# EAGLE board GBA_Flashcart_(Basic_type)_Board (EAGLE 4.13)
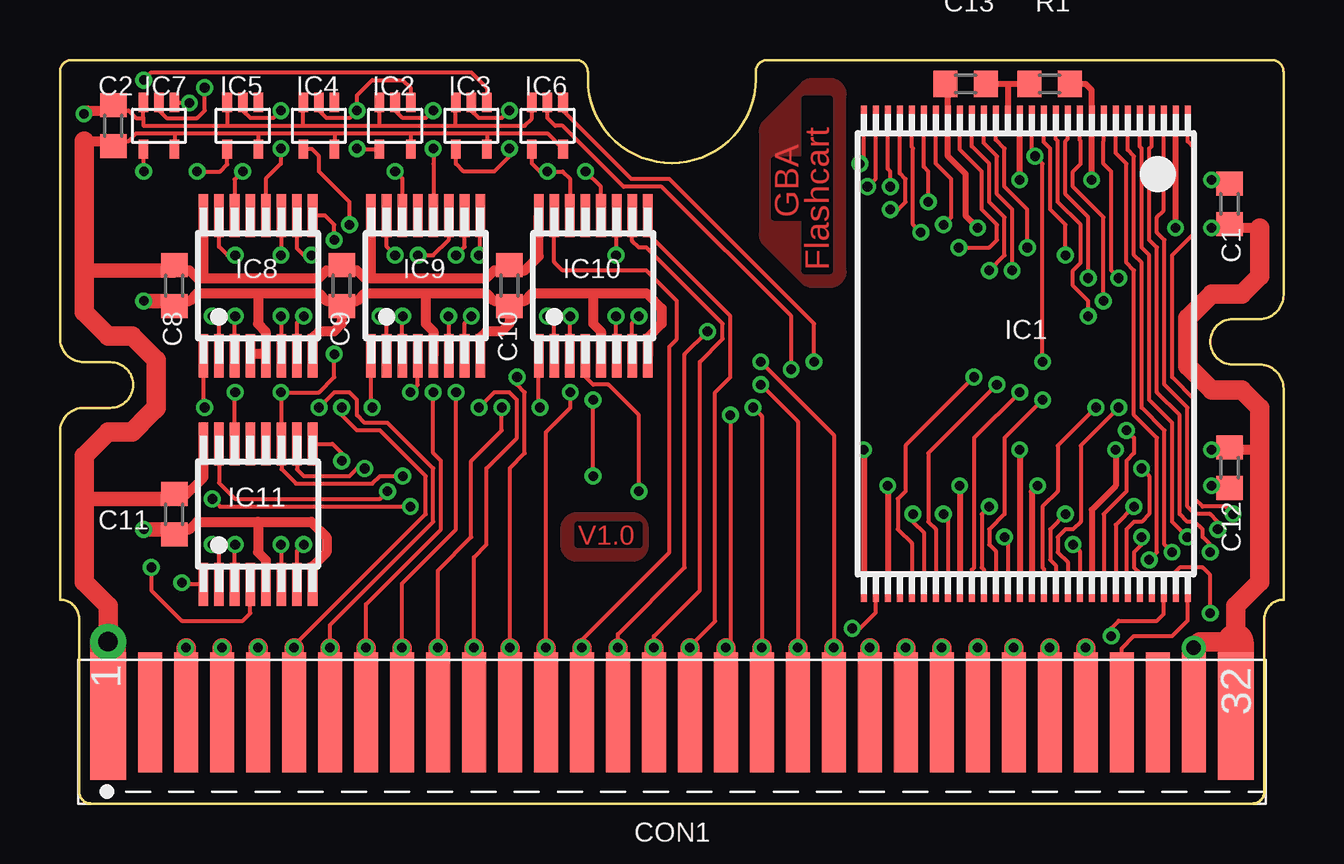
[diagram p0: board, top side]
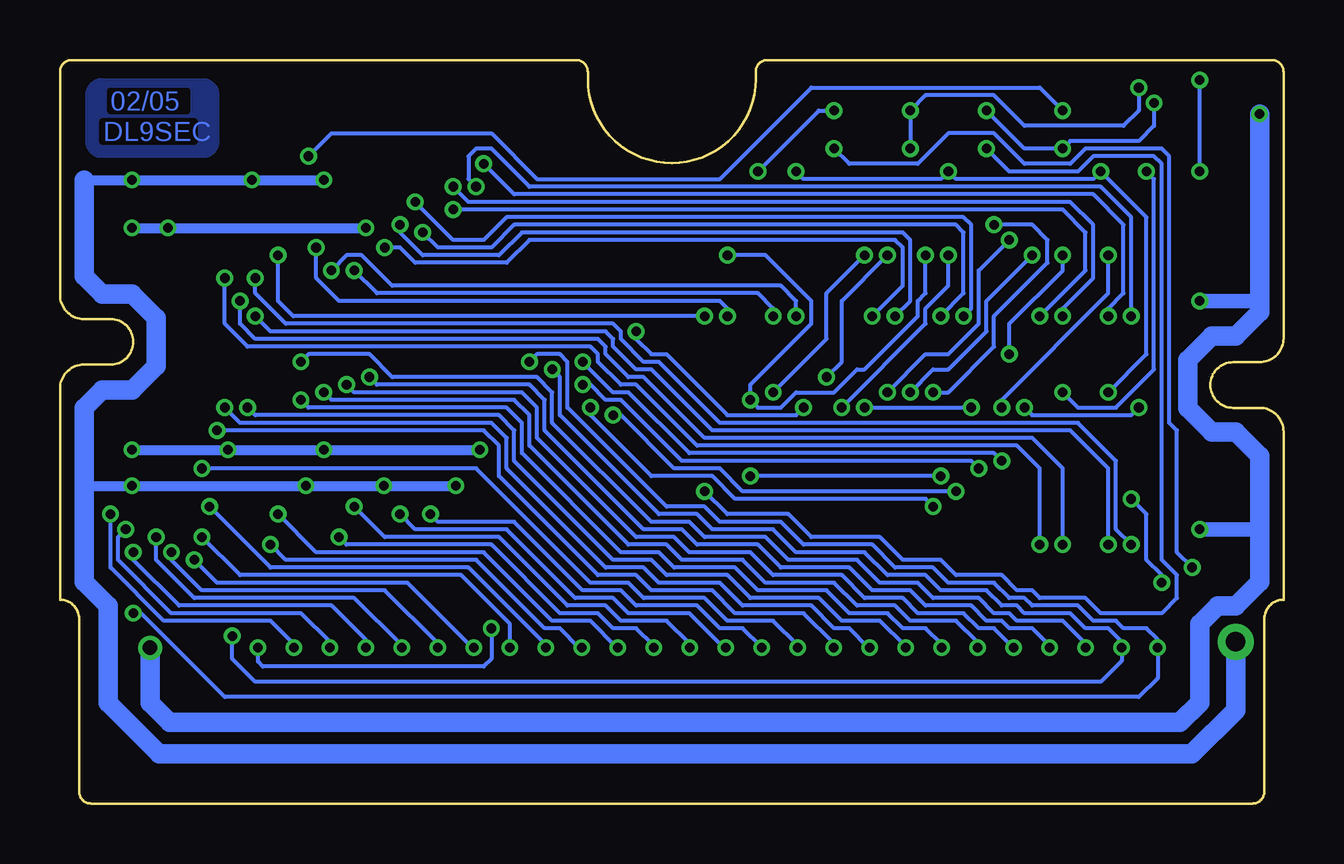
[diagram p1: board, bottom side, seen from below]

Size 51 x 31 mm. Coordinates in mm from the lower left corner, seen from the top.
Outline: 0.8,7.7 arc90 0,8.5 0,15.5 arc-90 1,16.5 2.1,16.5 arc180 2.1,18.4 1,18.4 arc-90 0,19.4 0,30.5 arc-90 0.5,31 21.5,31 arc-90 22,30.5 22,30.2 arc90 25.5,26.7 arc90 29,30.2 29,30.5 arc-90 29.5,31 50.5,31 arc-90 51,30.5 51,21.2 arc-90 50,20.2 48.9,20.2 arc180 48.9,18.3 50,18.3 arc-90 51,17.3 51,8.5 arc90 50.2,7.7 50.2,0.5 arc-90 49.7,0 1.3,0 arc-90 0.8,0.5 0.8,7.7
Copper layers (1*16): Top 0.035mm / dielectric 1.5mm / Bottom 0.035mm
Design rules "PCB-POOL": minimum track width 6mil, minimum drill 12mil, track to track 6mil, track to pad 6mil, pad to pad 6mil, via to via 6mil, smd to smd 6mil, copper to edge 18mil, drill to drill 8mil, minimum pad ring 8mil, minimum via ring 6mil, stop-mask expansion 3mil, vias tented up to drill 0mil, thermal gap 8mil

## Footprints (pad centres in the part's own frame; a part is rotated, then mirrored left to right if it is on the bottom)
0603 = smd 1 x 1.1: 1 -0.85,0; 2 0.85,0
GBACARTCON = smd 1.5 x 5.3: 1 1.25,3.65; 32 48.25,3.65 | smd 1 x 5: 2 3,3.8; 3 4.5,3.8; 4 6,3.8; 5 7.5,3.8; 6 9,3.8; 7 10.5,3.8; 8 12,3.8; 9 13.5,3.8; 10 15,3.8; 11 16.5,3.8; 12 18,3.8; 13 19.5,3.8; 14 21,3.8; 15 22.5,3.8; 16 24,3.8; 17 25.5,3.8; 18 27,3.8; 19 28.5,3.8; 20 30,3.8; 21 31.5,3.8; 22 33,3.8; 23 34.5,3.8; 24 36,3.8; 25 37.5,3.8; 26 39,3.8; 27 40.5,3.8; 28 42,3.8; 29 43.5,3.8; 30 45,3.8; 31 46.5,3.8
TSOP56 = smd 1.2 x 0.25: 1 -9.75,6.75; 2 -9.75,6.25; 3 -9.75,5.75; 4 -9.75,5.25; 5 -9.75,4.75; 6 -9.75,4.25; 7 -9.75,3.75; 8 -9.75,3.25; 9 -9.75,2.75; 10 -9.75,2.25; 11 -9.75,1.75; 12 -9.75,1.25; 13 -9.75,0.75; 14 -9.75,0.25; 15 -9.75,-0.25; 16 -9.75,-0.75; 17 -9.75,-1.25; 18 -9.75,-1.75; 19 -9.75,-2.25; 20 -9.75,-2.75; 21 -9.75,-3.25; 22 -9.75,-3.75; 23 -9.75,-4.25; 24 -9.75,-4.75; 25 -9.75,-5.25; 26 -9.75,-5.75; 27 -9.75,-6.25; 28 -9.75,-6.75; 29 9.75,-6.75; 30 9.75,-6.25; 31 9.75,-5.75; 32 9.75,-5.25; 33 9.75,-4.75; 34 9.75,-4.25; 35 9.75,-3.75; 36 9.75,-3.25; 37 9.75,-2.75; 38 9.75,-2.25; 39 9.75,-1.75; 40 9.75,-1.25; 41 9.75,-0.75; 42 9.75,-0.25; 43 9.75,0.25; 44 9.75,0.75; 45 9.75,1.25; 46 9.75,1.75; 47 9.75,2.25; 48 9.75,2.75; 49 9.75,3.25; 50 9.75,3.75; 51 9.75,4.25; 52 9.75,4.75; 53 9.75,5.25; 54 9.75,5.75; 55 9.75,6.25; 56 9.75,6.75
SOT353 = smd 0.4 x 0.8: 1 -0.65,-0.975; 2 0,-0.975; 3 0.65,-0.975; 4 0.65,0.975; 5 -0.65,0.975
TSSOP16 = smd 1.8 x 0.4: 1 -2.925,2.275; 2 -2.925,1.625; 3 -2.925,0.975; 4 -2.925,0.325; 5 -2.925,-0.325; 6 -2.925,-0.975; 7 -2.925,-1.625; 8 -2.925,-2.275; 9 2.925,-2.275; 10 2.925,-1.625; 11 2.925,-0.975; 12 2.925,-0.325; 13 2.925,0.325; 14 2.925,0.975; 15 2.925,1.625; 16 2.925,2.275

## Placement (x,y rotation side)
C1  100nF  [0603]  48.75,25 270 top
C2  100nF  [0603]  2.22,28.26 90 top
C8  100nF  [0603]  4.76,21.59 270 top
C9  100nF  [0603]  11.75,21.59 270 top
C10  100nF  [0603]  18.73,21.59 270 top
C11  100nF  [0603]  4.76,12.06 270 top
C12  100nF  [0603]  48.75,14 90 top
C13  opt.  [0603]  37.75,30 180 top
CON1  GBACARTCON  [GBACARTCON]  0.75,0 0 top
IC1  TE28F128J3C-120  [TSOP56]  40.25,18.75 270 top
IC2  74LVC1G00GW  [SOT353]  13.97,28.26 180 top
IC3  74LVC1G00GW  [SOT353]  17.14,28.26 180 top
IC4  74LVC1G04GW  [SOT353]  10.79,28.26 180 top
IC5  74LVC1G04GW  [SOT353]  7.62,28.26 180 top
IC6  74LVC1G08GW  [SOT353]  20.32,28.26 180 top
IC7  74LVC1G08GW  [SOT353]  4.13,28.26 180 top
IC8  74AC191MTC  [TSSOP16]  8.26,21.59 90 top
IC9  74AC191MTC  [TSSOP16]  15.24,21.59 90 top
IC10  74AC191MTC  [TSSOP16]  22.23,21.59 90 top
IC11  74AC191MTC  [TSSOP16]  8.26,12.06 90 top
R1  1k  [0603]  41.25,30 0 top

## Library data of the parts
C1 C2 C8-C13 R1 = Custom_II
CON1 = GBA_Cart
IC1-IC11 = GBA_Parts

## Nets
+3V3: C1.1 C2.1 C8.1 C9.1 C10.1 C11.1 C12.1 CON1.1 IC1.9 IC1.15 IC1.31 IC1.37 IC1.43 IC2.5 IC3.5 IC4.5 IC5.5 IC6.5 IC7.5 IC8.16 IC9.16 IC10.16 IC11.16 R1.2
A16: CON1.22 IC1.7
A17: CON1.23 IC1.6
A18: CON1.24 IC1.5
A19: CON1.25 IC1.4
A20: CON1.26 IC1.3
A21: CON1.27 IC1.1
A22: CON1.28 IC1.30
A23: CON1.29 IC1.56
AD0: CON1.6 IC1.33 IC8.15
AD1: CON1.7 IC1.35 IC8.1
AD2: CON1.8 IC1.38 IC8.10
AD3: CON1.9 IC1.40 IC8.9
AD4: CON1.10 IC1.44 IC9.15
AD5: CON1.11 IC1.46 IC9.1
AD6: CON1.12 IC1.49 IC9.10
AD7: CON1.13 IC1.51 IC9.9
AD8: CON1.14 IC1.34 IC10.15
AD9: CON1.15 IC1.36 IC10.1
AD10: CON1.16 IC1.39 IC10.10
AD11: CON1.17 IC1.41 IC10.9
AD12: CON1.18 IC1.45 IC11.15
AD13: CON1.19 IC1.47 IC11.1
AD14: CON1.20 IC1.50 IC11.10
AD15: CON1.21 IC1.52 IC11.9
ADR0: IC1.28 IC8.3
ADR1: IC1.27 IC8.2
ADR2: IC1.26 IC8.6
ADR3: IC1.25 IC8.7
ADR4: IC1.24 IC9.3
ADR5: IC1.23 IC9.2
ADR6: IC1.22 IC9.6
ADR7: IC1.20 IC9.7
ADR8: IC1.19 IC10.3
ADR9: IC1.18 IC10.2
ADR10: IC1.17 IC10.6
ADR11: IC1.13 IC10.7
ADR12: IC1.12 IC11.3
ADR13: IC1.11 IC11.2
ADR14: IC1.10 IC11.6
ADR15: IC1.8 IC11.7
GND: C1.2 C2.2 C8.2 C9.2 C10.2 C11.2 C12.2 C13.2 CON1.31 CON1.32 IC1.2 IC1.21 IC1.29 IC1.42 IC1.48 IC2.3 IC3.3 IC4.3 IC5.3 IC6.3 IC7.3 IC8.4 IC8.5 IC8.8 IC9.5 IC9.8 IC10.5 IC10.8 IC11.5 IC11.8
N$1: IC5.4 IC8.11 IC9.11 IC10.11 IC11.11
N$2: IC6.4 IC8.14 IC9.14 IC10.14 IC11.14
N$3: IC3.4 IC11.4
N$4: C13.1 IC1.16 R1.1
N$5: IC4.4 IC9.4
N$6: IC2.1 IC4.2 IC7.1 IC8.12
N$7: IC2.4 IC10.4
N$8: IC2.2 IC7.2 IC9.12
N$9: IC3.2 IC10.12
N$10: IC3.1 IC7.4
NCS_ROM: CON1.5 IC1.14 IC5.2
NRD: CON1.4 IC1.54 IC6.2
NWR: CON1.3 IC1.55 IC6.1

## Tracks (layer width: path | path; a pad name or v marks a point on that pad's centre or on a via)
+3V3  (via drill 0.4, 0.8 pad 1.5)
  Top 0.16: 1,27.62 0.95,27.62 | IC5.5 8.27,27.93 8.26,27.94 | C2.1 2.22,27.62 2.86,27.62 3.17,27.94 4.76,27.94 | IC6.5 20.32,27.94 17.78,27.94 | 4.76,27.94 8.26,27.94 | 8.26,27.94 11.43,27.94 | 11.43,27.94 14.61,27.94 | 14.61,27.94 17.78,27.94 | IC3.5 17.8,27.93 17.78,27.94 | IC2.5 14.62,27.93 14.61,27.94 | IC4.5 11.45,27.93 11.43,27.94 | IC7.5 4.78,27.93 4.76,27.94
  Top 0.25: v34.5,13.25 IC1.31 | v40.75,13.25 40.5,13 IC1.43 | 48.75,13.25 C12.1 | v43,26 IC1.9 43,29.75 42.75,30 R1.2 | v40,26 IC1.15 | C1.1 48.75,25.5 | v37.5,13.25 IC1.37 v37.5,13.25
  Top 0.406: v48,13.25 48.75,13.25 48.75,13 | v48,26 48.75,26 | 1,23.5 0.95,23.5 | 1,13.34 0.95,13.34 | 1,22.23 0.95,22.23 | 18.52,22.23 C10.1 18.73,22.23 | 1,12.7 0.95,12.7 | C11.1 4.76,12.7 5.08,12.7 5.98,13.6 IC11.16 | 1,27.62 2.22,27.62 | C8.1 4.76,22.23 5.4,22.23 5.71,21.91 6.03,21.91 | 6.03,21.91 10.79,21.91 11.11,22.23 11.75,22.23 | 11.75,22.23 C9.1 | IC8.16 5.98,21.96 6.03,21.91 | 11.75,22.23 12.38,22.23 12.7,21.91 13.02,21.91 | 13.02,21.91 17.78,21.91 18.1,22.23 18.73,22.23 | IC9.16 12.96,21.96 13.02,21.91 | 18.73,22.23 19.37,22.23 19.95,22.81 IC10.16 | 3.75,16.25
  Top 0.6: 1,12.7 4.76,12.7 | 1,22.23 4.76,22.23
  Top 0.61: C12.1 48.75,13 | 48.75,26 C1.1
  Top 0.813: v2,6.75 2,8.25 1,9.25 1,12.7 1,13.34 1,14.5 2,15.5 3,15.5 3.75,16.25 4,16.5 4,18.5 3,19.5 2,19.5 1,20.5 1,22.23 1,23.5 1,27.62
  Top 1.5: CON1.1 v2,6.75
  Bottom 0.406: v34.5,13.25 v37.5,13.25 v40.75,13.25 v48,13.25 50,13.25 | v40,26 v43,26 v48,26 50,26
  Bottom 0.813: v2,6.75 2,3.88 3.82,2.07 46.87,2.07 49,4.2 49,8.25 50,9.25 50,13.25 50,16.5 49.25,17.25 48,17.25 47,18.25 47,20.25 48,21.25 49.25,21.25 50,22 50,26
A16  (via drill 0.4)
  Top 0.16: IC1.7 44,27.12 44.45,26.67 44.45,22.54 44.77,22.23 44.77,16.19 45.72,15.24 45.72,10.48 v45.4,10.16
  Top 0.813: CON1.22 v33.75,6.5
  Bottom 0.16: v45.4,10.16 44.45,9.21 36.51,9.21 33.8,6.5 v33.75,6.5
A17  (via drill 0.4)
  Top 0.16: IC1.6 44.5,27.25 44.77,26.99 44.77,22.86 45.09,22.54 45.09,16.51 46.04,15.56 46.04,10.79 v46.35,10.48
  Top 0.813: CON1.23 v35.25,6.5
  Bottom 0.16: v46.35,10.48 46.35,10.16 45.09,8.89 37.47,8.89 35.25,6.67 v35.25,6.5
A18  (via drill 0.4)
  Top 0.16: v46.99,11.11 46.35,11.75 46.35,15.88 45.4,16.83 45.4,22.86 45.09,23.18 45.09,27.3 45,27.39 IC1.5
  Top 0.813: CON1.24 v36.75,6.5
  Bottom 0.16: v36.75,6.5 36.75,6.59 38.73,8.57 45.4,8.57 46.99,10.16 v46.99,11.11
A19  (via drill 0.4)
  Top 0.16: v47.94,10.48 47.94,10.79 47.62,11.11 47.62,11.43 47.31,11.75 46.99,11.75 46.67,12.06 46.67,16.19 45.72,17.14 45.72,23.18 45.4,23.5 45.4,27.3 45.5,27.4 IC1.4
  Top 0.813: CON1.25 v38.25,6.5
  Bottom 0.16: v38.25,6.5 38.25,6.82 39.69,8.26 46.04,8.26 47.94,10.16 v47.94,10.48
A20  (via drill 0.4)
  Top 0.16: v48.26,11.43 48.26,11.75 47.94,12.06 47.31,12.06 46.99,12.38 46.99,16.51 46.04,17.46 46.04,23.5 45.72,23.81 45.72,24.45 46,24.73 IC1.3
  Top 0.813: CON1.26 v39.75,6.5
  Bottom 0.16: v39.75,6.5 39.75,6.73 40.96,7.94 46.35,7.94 48.58,10.16 48.58,11.11 v48.26,11.43
A21  (via drill 0.4)
  Top 0.16: IC1.1 47,27.61 47.31,27.3 47.31,23.81 46.35,22.86 46.35,17.78 47.31,16.83 47.31,12.7 47.62,12.38 48.58,12.38 v48.9,12.06
  Top 0.813: CON1.27 v41.25,6.5
  Bottom 0.16: v41.25,6.5 41.25,6.64 42.23,7.62 46.67,7.62 48.9,9.84 v48.9,12.06
A22  (via drill 0.4)
  Top 0.16: IC1.30 34,7.96 33.34,7.3 v33.02,7.3
  Top 0.813: v42.75,6.5 CON1.28
  Bottom 0.16: v42.75,6.5 42.75,5.92 42.55,5.71 33.34,5.71 33.02,6.03 v33.02,7.3
A23
  Top 0.16: CON1.29 44.25,6.47 44.77,6.99 46.35,6.99 47,7.63 IC1.56
AD0  (via drill 0.4)
  Top 0.16: IC1.33 35.5,10.86 34.92,11.43 34.92,12.7 35.24,13.02 35.24,14.92 v38.1,17.78 | 9.75,6.58 v9.75,6.5 9.84,6.59 9.84,6.67 15.24,12.06 15.24,13.65 13.34,15.56 12.38,15.56 11.75,16.19 v11.75,16.51 | v7.3,22.86 6.99,22.86 6.63,23.21 IC8.15
  Top 0.813: CON1.6 v9.75,6.5
  Bottom 0.16: v38.1,17.78 37.78,17.46 31.43,17.46 30.8,16.83 30.8,15.56 26.67,11.43 25.08,11.43 24.45,10.79 21.91,10.79 20.95,9.84 18.1,9.84 17.14,8.89 15.56,8.89 14.92,8.26 13.02,8.26 12.38,7.62 11.75,7.62 11.43,7.3 10.48,7.3 9.75,6.58 v9.75,6.5 | v7.3,22.86 7.3,21.27 11.75,16.83 v11.75,16.51
AD1  (via drill 0.4)
  Top 0.16: IC1.35 36.5,11.44 36.2,11.75 36.2,14.61 v39.05,17.46 | IC8.1 5.98,16.56 v6.03,16.51 | v10.79,16.51 11.43,17.14 12.06,17.14 12.38,16.83 12.38,16.19 12.7,15.88 13.65,15.88 15.56,13.97 15.56,11.75 11.25,7.44 v11.25,6.5
  Top 0.813: CON1.7 v11.25,6.5
  Bottom 0.16: v39.05,17.46 38.73,17.14 31.75,17.14 31.11,16.51 31.11,15.24 26.99,11.11 25.4,11.11 24.77,10.48 22.23,10.48 21.27,9.53 18.41,9.53 17.46,8.57 15.88,8.57 15.24,7.94 13.34,7.94 12.7,7.3 12.06,7.3 11.26,6.5 v11.25,6.5 | v10.79,16.51 10.48,16.19 6.35,16.19 v6.03,16.51
AD2  (via drill 0.4)
  Top 0.16: IC1.38 38,9.74 38.1,9.84 38.1,15.24 v40.01,17.14 | v15.56,17.14 15.56,14.61 15.88,14.29 15.88,11.43 12.75,8.3 v12.75,6.5 | v10.48,22.86 10.16,22.86 9.88,23.14 IC8.10
  Top 0.813: CON1.8 v12.75,6.5
  Bottom 0.16: v40.01,17.14 39.69,16.83 32.07,16.83 31.43,16.19 31.43,14.92 27.3,10.79 25.72,10.79 25.08,10.16 22.54,10.16 21.59,9.21 18.73,9.21 17.78,8.26 16.19,8.26 15.56,7.62 13.65,7.62 12.75,6.72 v12.75,6.5 | v15.56,17.14 14.61,18.1 13.97,18.1 12.38,19.68 12.38,20.95 v10.48,22.86
AD3  (via drill 0.4)
  Top 0.16: IC1.40 39,10.53 38.73,10.79 38.73,11.43 39.37,12.06 39.37,15.24 v40.96,16.83 | v16.51,17.14 16.51,11.43 14.25,9.17 v14.25,6.5 | v11.43,23.5 11.43,24.13 11.04,24.52 IC8.9
  Top 0.813: CON1.9 v14.25,6.5
  Bottom 0.16: v40.96,16.83 40.64,16.51 32.38,16.51 31.75,15.88 31.75,14.61 27.62,10.48 26.04,10.48 25.4,9.84 22.86,9.84 21.91,8.89 19.05,8.89 18.1,7.94 16.51,7.94 15.88,7.3 14.92,7.3 14.25,6.63 v14.25,6.5 | v16.51,17.14 14.92,18.73 13.97,18.73 12.7,20 12.7,22.23 v11.43,23.5
AD4  (via drill 0.4)
  Top 0.16: IC1.44 41,9.8 40.96,9.84 40.96,12.38 41.59,13.02 41.59,14.92 v43.18,16.51 | IC9.15 13.62,23.21 v13.97,22.86 | v18.41,16.51 18.41,15.56 17.14,14.29 17.14,11.11 15.75,9.72 v15.75,6.5
  Top 0.813: CON1.10 v15.75,6.5
  Bottom 0.16: v43.18,16.51 42.86,16.19 32.7,16.19 32.07,15.56 32.07,14.29 27.94,10.16 26.35,10.16 25.72,9.53 23.18,9.53 22.23,8.57 19.37,8.57 18.41,7.62 16.83,7.62 15.75,6.54 v15.75,6.5 | v13.97,22.86 13.97,21.59 14.92,20.64 14.92,20 v18.41,16.51
AD5  (via drill 0.4)
  Top 0.16: IC1.46 42,10.07 41.59,10.48 41.59,11.11 41.91,11.43 42.23,11.43 42.55,11.75 42.55,14.92 v44.13,16.51 | IC9.1 12.96,16.56 v13.02,16.51 | v17.46,16.51 18.1,17.14 18.73,17.14 19.05,16.83 19.05,15.24 17.78,13.97 17.78,10.79 17.25,10.27 v17.25,6.5
  Top 0.813: CON1.11 v17.25,6.5
  Bottom 0.16: v44.13,16.51 43.5,15.88 33.02,15.88 32.38,15.24 32.38,13.97 28.26,9.84 26.67,9.84 26.04,9.21 23.5,9.21 22.54,8.26 19.68,8.26 18.73,7.3 18.1,7.3 17.3,6.5 v17.25,6.5 | v17.46,16.51 v13.02,16.51
AD6  (via drill 0.4)
  Top 0.16: IC1.49 43.5,12.07 44.45,13.02 44.45,14.29 44.77,14.61 44.77,15.24 v44.45,15.56 | IC9.10 16.86,23.21 v16.51,22.86 | v19.05,17.78 19.05,17.46 19.37,17.14 19.37,14.61 18.75,13.99 v18.75,6.5
  Top 0.813: CON1.12 v18.75,6.5
  Bottom 0.16: v44.45,15.56 33.34,15.56 32.7,14.92 32.7,13.65 28.57,9.53 26.99,9.53 26.35,8.89 23.81,8.89 22.86,7.94 20,7.94 18.75,6.68 v18.75,6.5 | v16.51,22.86 18.41,20.95 18.41,18.41 v19.05,17.78
AD7  (via drill 0.4)
  Top 0.16: IC1.51 44.5,9.47 44.45,9.53 44.45,11.43 44.77,11.75 45.09,11.75 45.4,12.06 45.4,13.65 v45.09,13.97 | IC9.9 17.52,22.91 v17.46,22.86 | v21.27,17.14 21.27,16.51 20.25,15.49 v20.25,6.5
  Top 0.813: CON1.13 v20.25,6.5
  Bottom 0.16: v45.09,13.97 33.66,13.97 28.89,9.21 27.3,9.21 26.67,8.57 24.13,8.57 23.18,7.62 21.27,7.62 20.25,6.6 v20.25,6.5 | v17.46,22.86 19.05,21.27 19.05,19.37 v21.27,17.14
AD8  (via drill 0.4)
  Top 0.16: IC1.34 36,11.31 35.56,11.75 v35.56,12.06 | IC10.15 20.6,22.58 20.95,22.23 24.45,22.23 25.72,20.95 25.72,19.37 25.4,19.05 25.4,10.48 21.75,6.83 v21.75,6.5
  Top 0.813: CON1.14 v21.75,6.5
  Bottom 0.16: v35.56,12.06 35.24,11.75 32.07,11.75 29.21,8.89 27.62,8.89 26.99,8.26 24.45,8.26 23.5,7.3 22.54,7.3 v21.75,6.51 v21.75,6.5
AD9  (via drill 0.4)
  Top 0.16: IC1.36 37,11.89 v36.83,12.06 | IC10.1 19.95,16.56 v20,16.51 | v26.99,19.68 26.04,18.73 26.04,9.84 23.25,7.06 v23.25,6.5
  Top 0.813: CON1.15 v23.25,6.5
  Bottom 0.16: v36.83,12.06 36.2,11.43 32.38,11.43 29.53,8.57 27.94,8.57 27.3,7.94 24.77,7.94 23.33,6.5 v23.25,6.5 | v26.99,19.68 26.99,19.37 26.35,18.73 25.72,18.73 23.18,16.19 20.32,16.19 v20,16.51
AD10  (via drill 0.4)
  Top 0.16: IC1.39 38.5,9.76 38.42,9.84 38.42,12.06 v38.73,12.38 | v24.75,6.5 24.75,6.97 26.67,8.89 26.67,18.41 27.62,19.37 27.62,20 24.45,23.18 24.13,23.18 23.85,23.46 IC10.10
  Top 0.813: CON1.16 v24.75,6.5
  Bottom 0.16: v38.73,12.38 37.47,11.11 32.7,11.11 29.84,8.26 28.26,8.26 27.62,7.62 25.72,7.62 24.75,6.65 v24.75,6.5
AD11  (via drill 0.4)
  Top 0.16: IC1.41 39.5,10.98 v39.37,11.11 | v26.25,6.5 26.2,6.5 27.3,7.6 27.3,17.14 27.94,17.78 27.94,20.32 24.5,23.76 IC10.9
  Top 0.813: CON1.17 v26.25,6.5
  Bottom 0.16: v39.37,11.11 39.05,10.79 33.02,10.79 30.16,7.94 28.57,7.94 27.94,7.3 26.99,7.3 26.25,6.57 v26.25,6.5
AD12  (via drill 0.4)
  Top 0.16: IC1.45 41.5,9.94 41.27,10.16 41.27,11.43 v41.91,12.06 | IC11.15 6.63,13.37 7.3,12.7 13.34,12.7 v13.65,13.02 | 27.75,6.48 27.94,6.67 v27.94,16.19
  Top 0.813: CON1.18 27.75,6.48 v27.75,6.5
  Bottom 0.16: v41.91,12.06 40.32,10.48 33.34,10.48 30.48,7.62 28.89,7.62 27.77,6.5 v27.75,6.5 | v13.65,13.02 22.54,13.02 23.5,13.97 25.4,13.97 27.62,16.19 v27.94,16.19
AD13  (via drill 0.4)
  Top 0.16: IC1.47 42.5,10.52 v42.23,10.79 | IC11.1 5.15,9.14 v5.08,9.21 | v6.35,12.7 6.67,12.38 v14.61,12.38 | v29.25,6.5 29.25,16.15 v28.89,16.51
  Top 0.813: v29.25,6.5 CON1.19
  Bottom 0.16: v42.23,10.79 41.59,10.16 33.66,10.16 30.8,7.3 30.16,7.3 29.36,6.5 v29.25,6.5 | v14.61,12.38 14.92,12.7 22.86,12.7 23.81,13.65 26.35,13.65 28.89,16.19 v28.89,16.51 | v5.08,9.21 5.08,9.53 5.71,10.16 5.71,12.06 v6.35,12.7
AD14  (via drill 0.4)
  Top 0.16: IC1.50 44,11.62 v44.77,12.38 | IC11.10 9.88,13.93 10.16,13.65 12.06,13.65 12.38,13.97 v12.7,13.97 | v30.75,6.5 30.75,15.92 v29.21,17.46
  Top 0.813: v30.75,6.5 CON1.20
  Bottom 0.16: v44.77,12.38 42.23,9.84 33.97,9.84 30.75,6.62 v30.75,6.5 | v12.7,13.97 13.02,14.29 25.08,14.29 27.62,16.83 28.26,16.83 28.89,17.46 v29.21,17.46
AD15  (via drill 0.4)
  Top 0.16: IC1.52 45,9.61 44.77,9.84 44.77,10.48 45.09,10.79 v45.09,11.11 | v32.25,6.5 32.25,15.38 v29.21,18.41 | v11.75,14.29 11.75,14.61 11.36,14.99 IC11.9
  Top 0.813: v32.25,6.5 CON1.21
  Bottom 0.16: v45.09,11.11 43.5,9.53 34.29,9.53 32.25,7.49 v32.25,6.5 | v11.75,14.29 12.06,14.61 24.77,14.61 27.3,17.14 27.94,17.14 v29.21,18.41
ADR0  (via drill 0.4)
  Top 0.16: IC1.28 33.5,26.83 v33.34,26.67 | IC8.3 7.28,20.3 v7.3,20.32
  Bottom 0.16: v33.34,26.67 32.07,25.4 7.94,25.4 6.67,24.13 6.67,21.27 7.3,20.64 v7.3,20.32
ADR1  (via drill 0.4)
  Top 0.16: IC1.27 34,26.06 v33.66,25.72 | IC8.2 6.63,20.04 v6.35,20.32
  Bottom 0.16: v6.35,20.32 6.35,24.45 7.62,25.72 31.43,25.72 33.02,27.3 33.66,27.3 33.97,26.99 33.97,26.04 v33.66,25.72
ADR2  (via drill 0.4)
  Top 0.16: IC8.6 9.23,20.3 v9.21,20.32 | v34.61,25.72 34.61,26.35 34.5,26.46 IC1.26
  Bottom 0.16: v9.21,20.32 9.21,20.64 7.94,21.91 7.94,24.13 8.89,25.08 33.97,25.08 v34.61,25.72
ADR3  (via drill 0.4)
  Top 0.16: IC8.7 9.88,20.04 v10.16,20.32 | IC1.25 35,26.28 35.24,26.04 35.24,25.08 34.92,24.77 v34.61,24.77
  Bottom 0.16: v10.16,20.32 8.26,22.23 8.26,23.81 9.21,24.77 v34.61,24.77
ADR4  (via drill 0.4)
  Top 0.16: IC1.24 35.5,27.36 35.56,27.3 35.56,24.13 v35.88,23.81 | IC9.3 14.27,20.3 v14.29,20.32
  Bottom 0.16: v14.29,20.32 13.34,21.27 13.34,23.81 13.65,24.13 32.07,24.13 33.02,23.18 35.24,23.18 v35.88,23.81
ADR5  (via drill 0.4)
  Top 0.16: IC9.2 13.62,20.04 v13.34,20.32 | v36.2,25.08 36.2,26.35 36,26.55 IC1.23
  Bottom 0.16: v13.34,20.32 13.02,20.64 13.02,24.13 13.34,24.45 32.38,24.45 33.34,23.5 34.61,23.5 v36.2,25.08
ADR6  (via drill 0.4)
  Top 0.16: IC1.22 36.5,26.68 37.15,26.04 37.15,24.45 v36.83,24.13 | IC9.6 16.21,20.3 v16.19,20.32
  Bottom 0.16: v16.19,20.32 15.56,20.95 15.56,23.5 15.88,23.81 31.75,23.81 32.7,22.86 35.88,22.86 36.83,23.81 v36.83,24.13
ADR7  (via drill 0.4)
  Top 0.16: IC9.7 16.86,20.04 v17.14,20.32 | IC1.20 37.5,27.27 38.42,26.35 38.42,24.77 39.05,24.13 39.05,23.5 38.73,23.18 v37.47,23.18
  Bottom 0.16: v17.14,20.32 15.88,21.59 15.88,23.18 16.19,23.5 31.43,23.5 32.38,22.54 36.2,22.54 36.83,23.18 v37.47,23.18
ADR8  (via drill 0.4)
  Top 0.16: IC1.19 38,27.41 38.73,26.67 38.73,25.08 39.37,24.45 39.37,22.86 v38.73,22.23 | IC10.3 21.25,20.3 v21.27,20.32
  Bottom 0.16: v21.27,20.32 21.27,20.64 21.91,21.27 37.78,21.27 v38.73,22.23
ADR9  (via drill 0.4)
  Top 0.16: IC1.18 38.5,27.54 39.05,26.99 39.05,25.4 39.69,24.77 v39.69,22.23 | IC10.2 20.6,20.04 v20.32,20.32
  Bottom 0.16: v20.32,20.32 20.32,20.95 20.95,21.59 37.15,21.59 38.42,22.86 39.05,22.86 v39.69,22.23
ADR10  (via drill 0.4)
  Top 0.16: IC1.17 39,27.68 39.37,27.3 39.37,25.72 40.32,24.77 v40.32,23.18 | IC10.6 23.2,18.71 23.18,18.73 v23.18,20.32
  Bottom 0.16: v23.18,20.32 23.18,20.64 23.5,20.95 39.37,20.95 40.32,21.91 v40.32,23.18
ADR11  (via drill 0.4)
  Top 0.16: IC1.13 41,27.58 41.27,27.3 41.27,24.77 41.91,24.13 v41.91,22.86 | IC10.7 23.85,20.04 v24.13,20.32
  Bottom 0.16: v24.13,20.32 41.27,20.32 41.91,20.95 v41.91,22.86
ADR12  (via drill 0.4)
  Top 0.16: IC1.12 41.5,27.71 41.59,27.62 41.59,25.08 42.55,24.13 42.55,22.54 42.23,22.23 42.23,21.59 42.86,20.95 v42.86,20.32 | IC11.3 7.28,10.77 v7.3,10.79
  Bottom 0.16: v7.3,10.79 7.3,13.97 8.89,15.56 23.81,15.56 26.35,18.1 26.99,18.1 27.94,19.05 27.94,19.37 28.26,19.68 42.23,19.68 v42.86,20.32
ADR13  (via drill 0.4)
  Top 0.16: IC1.11 42,27.71 41.91,27.62 41.91,25.4 42.86,24.45 v42.86,21.91 | IC11.2 6.63,10.52 v6.35,10.79
  Bottom 0.16: v6.35,10.79 6.99,11.43 6.99,14.29 8.57,15.88 23.5,15.88 26.04,18.41 26.67,18.41 27.62,19.37 27.62,19.68 27.94,20 41.59,20 42.86,21.27 v42.86,21.91
ADR14  (via drill 0.4)
  Top 0.16: IC1.10 42.5,27.67 42.55,27.62 42.55,26.67 42.23,26.35 42.23,25.72 43.5,24.45 v43.5,20.95 | IC11.6 9.23,10.77 v9.21,10.79
  Bottom 0.16: v9.21,10.79 9.21,13.97 10.48,15.24 24.13,15.24 26.67,17.78 27.3,17.78 28.26,18.73 28.26,19.05 28.57,19.37 42.86,19.37 43.5,20 v43.5,20.95
ADR15  (via drill 0.4)
  Top 0.16: IC1.8 43.5,27.62 43.5,26.67 43.81,26.35 43.81,22.23 v44.13,21.91 | IC11.7 9.88,10.52 v10.16,10.79
  Bottom 0.16: v10.16,10.79 10.16,13.97 11.11,14.92 24.45,14.92 26.99,17.46 27.62,17.46 28.57,18.41 28.57,18.73 28.89,19.05 43.18,19.05 44.13,20 v44.13,21.91
GND  (via drill 0.4, 0.6 pad 1)
  Top 0.16: IC5.3 6.99,29.21 6.99,28.26 | C2.2 2.22,28.89 2.86,28.89 3.17,28.57 3.48,28.57 | 6.99,28.26 3.49,28.26 3.48,28.27 3.48,28.57 | 6.99,28.26 10.16,28.26 | 10.16,28.26 13.34,28.26 | 13.34,28.26 16.51,28.26 | 16.51,28.26 19.37,28.26 19.67,28.56 IC6.3 | IC3.3 16.5,28.27 16.51,28.26 | IC2.3 13.32,28.27 13.34,28.26 | IC4.3 10.14,28.27 10.16,28.26 | 3.48,28.57 IC7.3
  Top 0.2: IC5.3 6.97,29.2
  Top 0.25: C13.2 37,30 IC1.21 37,27 37.75,26.25 37.75,24.5 v38.25,24 | v33.5,14.75 IC1.29 | v44,14.75 44,13.25 43,12.25 IC1.48 | v46.5,24 IC1.2 | v40,14.75 IC1.42 v40,14.75
  Top 0.406: 48.75,14.75 v48,14.75 | v48,24 48.75,24 50,24 | C12.2 48.9,14.75 50,14.75 | 8.57,18.73 8.57,18.67 IC8.5 | IC8.4 8,18.73 8.57,18.73 | C11.2 4.76,11.43 5.4,11.43 5.71,11.75 8.26,11.75 | v1,28.75 1.14,28.89 2.22,28.89 | C8.2 4.76,20.95 5.4,20.95 5.71,21.27 8.26,21.27 | 8.26,21.27 10.79,21.27 11.11,20.95 11.75,20.95 | 11.75,20.95 C9.2 11.75,20 11.43,19.68 10.79,19.68 10.53,19.42 IC8.8 | 11.75,20.95 12.38,20.95 12.7,21.27 15.24,21.27 | 15.24,21.27 15.56,21.27 | 15.56,21.27 17.78,21.27 18.1,20.95 18.73,20.95 | 18.73,20.95 C10.2 18.73,20 18.41,19.68 17.78,19.68 17.52,19.42 IC9.8 | 15.56,21.27 | 18.73,20.95 19.37,20.95 19.68,21.27 22.23,21.27 | 22.23,21.27 22.54,21.27 | 22.54,21.27 24.45,21.27 25.08,20.64 25.08,20 24.5,19.42 IC10.8 | 22.54,21.27 22.55,21.27 | 8.57,18.73 8.57,19.68 8.26,20 8.26,21.27 | IC9.5 15.56,19.68 15.24,20 15.24,21.27 | IC10.5 22.55,19.68 22.23,20 22.23,21.27 | IC11.8 10.53,9.89 11.11,10.48 11.11,11.11 10.48,11.75 8.26,11.75 | IC11.5 8.58,10.15 8.26,10.48 8.26,11.75
  Top 0.6: v3.49,11.43 4.76,11.43 | v3.49,20.95 4.76,20.95
  Top 0.61: C12.2 48.75,14.75 | 48.75,24 C1.2
  Top 0.813: CON1.31 v47.25,6.5 47.5,6.75 49,6.75 49,8.25 50,9.25 50,14.75 50,16.5 49.25,17.25 48,17.25 47,18.25 47,20.25 48,21.25 49.25,21.25 50,22 50,24
  Top 1.5: 49,6.75 CON1.32
  Bottom 0.406: v48,24 v46.5,24 v38.25,24 | v33.5,14.75 v40,14.75 v44,14.75 v48,14.75 | 2.86,19.5 2.86,19.68 | 1,20.95 0.95,20.95 | 1,11.43 0.95,11.43
  Bottom 0.6: 1,20.95 v3.49,20.95 | 1,11.43 v3.49,11.43
  Bottom 0.813: v47.25,6.5 47.25,4.2 46.43,3.38 4.32,3.38 3.5,4.2 3.5,7.5 2.75,8.25 2,8.25 1,9.25 1,11.43 1,14.5 2,15.5 3,15.5 4,16.5 4,18.5 3,19.5 2.86,19.5 2,19.5 1,20.5 1,20.95 v1,28.75
N$1  (via drill 0.4)
  Top 0.16: IC8.11 9.23,22.88 v9.21,22.86 | v11.43,18.73 11.43,17.78 10.79,17.14 v9.21,17.14 9.23,17.12 IC11.11 9.23,13.95 9.84,13.34 13.02,13.34 13.34,13.65 v14.29,13.65 | IC9.11 16.21,23.52 15.56,22.86 v14.92,22.86 | IC10.11 23.2,22.88 v23.18,22.86 | v22.23,13.65 v22.23,16.83 | IC5.4 6.97,26.66 6.67,26.35 v5.71,26.35
  Bottom 0.16: v9.21,22.86 9.21,22.23 11.43,20 v11.43,18.73 | v5.71,26.35 5.4,26.04 5.4,18.1 6.99,16.51 8.57,16.51 v9.21,17.14 | v14.92,22.86 14.92,21.27 15.24,20.95 15.24,20.32 17.46,18.1 17.78,18.1 18.73,17.14 20.32,17.14 20.95,16.51 21.91,16.51 v22.23,16.83 22.23,17.46 19.68,20 19.68,20.95 21.59,22.86 v23.18,22.86 | v14.29,13.65 v22.23,13.65
N$2  (via drill 0.4)
  Top 0.16: IC9.14 14.27,26.06 v13.97,26.35 | IC8.14 7.28,26.01 v7.62,26.35 | IC11.14 7.28,17.12 v7.3,17.14 | IC10.14 21.25,26.06 20.95,26.35 v20.32,26.35 20,26.35 19.67,26.68 IC6.4
  Bottom 0.16: v7.3,17.14 5.71,18.73 5.71,24.45 v7.62,26.35 7.94,26.04 13.65,26.04 v13.97,26.35 14.29,26.04 20,26.04 v20.32,26.35
N$3  (via drill 0.4)
  Top 0.16: IC11.4 7.93,7.93 7.62,7.62 5.08,7.62 3.81,8.89 v3.81,9.84 | v18.73,27.3 18.73,26.99 18.1,26.35 16.83,26.35 16.51,26.67 16.51,27.3 IC3.4
  Bottom 0.16: v3.81,9.84 4.45,10.48 4.45,15.56 4.76,15.88 4.76,26.99 5.08,27.3 8.26,27.3 8.89,26.67 10.79,26.67 12.06,27.94 13.97,27.94 15.24,26.67 18.1,26.67 v18.73,27.3
N$4
  Top 0.25: 39.5,30 IC1.16 | 40.5,30 R1.1 39.5,30 | 39.5,30 C13.1
N$5  (via drill 0.4)
  Top 0.16: IC9.4 14.91,17.45 v14.61,17.14 | v12.06,24.13 12.06,25.08 10.79,26.35 10.79,26.99 10.5,27.28 IC4.4
  Bottom 0.16: v14.61,17.14 13.97,17.14 12.06,19.05 12.06,20.32 9.84,22.54 9.84,23.5 10.48,24.13 v12.06,24.13
N$6  (via drill 0.4)
  Top 0.16: IC8.12 8.58,26.04 9.21,26.67 v9.21,27.3 | IC7.1 4.76,29.21 v5.4,29.21 | IC4.2 10.79,28.89 11.11,28.57 12.06,28.57 v12.38,28.89 12.38,29.53 13.02,30.16 14.29,30.16 14.61,29.84 14.61,29.21 IC2.1
  Bottom 0.16: v12.38,28.89 10.79,27.3 v9.21,27.3 8.89,27.62 6.03,27.62 5.4,28.26 v5.4,29.21
N$7  (via drill 0.4)
  Top 0.16: IC2.4 12.4,27.28 v12.38,27.3 | v24.13,13.02 24.13,16.19 22.86,17.46 22.23,17.46 21.91,17.78 21.91,18.41 21.9,18.42 IC10.4
  Bottom 0.16: v12.38,27.3 11.43,26.35 8.57,26.35 7.94,26.99 5.4,26.99 5.08,26.67 5.08,10.16 4.45,9.53 4.45,8.57 5.08,7.94 7.62,7.94 8.26,8.57 10.16,8.57 10.48,8.89 11.11,8.89 11.75,9.53 13.65,9.53 14.29,10.16 15.88,10.16 16.83,11.11 19.68,11.11 20.64,12.06 23.18,12.06 v24.13,13.02
N$8  (via drill 0.4)
  Top 0.16: IC9.12 15.56,26.66 v15.56,27.3 | v15.56,28.89 15.24,28.57 14.29,28.57 13.97,28.89 IC2.2 | IC7.2 4.13,28.89 4.45,28.57 5.71,28.57 6.03,28.89 v6.03,29.84
  Bottom 0.16: v15.56,27.3 v15.56,28.89 14.92,29.53 12.06,29.53 10.79,28.26 6.67,28.26 6.03,28.89 v6.03,29.84
N$9  (via drill 0.4)
  Top 0.16: IC10.12 22.55,25.71 v21.91,26.35 | v18.73,28.89 18.41,28.57 17.46,28.57 17.14,28.89 IC3.2
  Bottom 0.16: v21.91,26.35 19.37,28.89 v18.73,28.89
N$10  (via drill 0.4)
  Top 0.16: IC3.1 17.8,29.83 17.14,30.48 3.81,30.48 v3.49,30.16 | IC7.4 3.48,26.37 v3.49,26.35
  Bottom 0.16: v3.49,26.35 v3.49,30.16
N$11
  pour Top: 32.7,29.56 arc90 32.1,30.16 31.36,30.16 arc45 30.94,29.99 29.39,28.43 arc45 29.21,28.01 29.21,23.74 arc45 29.39,23.32 30.94,21.77 arc45 31.36,21.59 32.1,21.59 arc90 32.7,22.19
N$12
  pour Top: 23.85,12.06 arc-90 24.45,11.46 24.45,10.76 arc-90 23.85,10.16 21.55,10.16 arc-90 20.95,10.76 20.95,11.46 arc-90 21.55,12.06
N$13
  pour Bottom: 49.25,26.99 arc90 49.85,27.59 49.85,29.56 arc90 49.25,30.16 45.05,30.16 arc90 44.45,29.56 44.45,27.59 arc90 45.05,26.99
NCS_ROM  (via drill 0.4)
  Top 0.16: IC1.14 40.5,27.13 v40.64,26.99 40.96,26.67 v40.96,18.41 | 7.62,29.21 IC5.2 7.62,28.89 7.94,28.57 8.89,28.57 v9.21,28.89
  Top 0.813: CON1.5 v8.25,6.5
  Bottom 0.16: v40.64,26.99 39.69,27.94 33.02,27.94 31.11,26.04 23.5,26.04 19.68,29.84 10.16,29.84 v9.21,28.89 | v8.25,6.5 8.25,6.66 9.21,7.62 11.11,7.62 11.43,7.94 12.06,7.94 12.7,8.57 14.61,8.57 15.24,9.21 16.83,9.21 17.78,10.16 20.64,10.16 21.59,11.11 24.13,11.11 24.77,11.75 26.35,11.75 30.48,15.88 30.48,17.14 31.11,17.78 37.15,17.78 38.1,18.73 40.64,18.73 v40.96,18.41
NRD  (via drill 0.4)
  Top 0.16: CON1.4 v6.75,6.5 | IC6.2 20.32,28.57 20.64,28.26 20.95,28.26 23.5,25.72 25.08,25.72 30.48,20.32 v30.48,18.1 | v43.81,6.99 43.81,7.3 44.13,7.62 45.72,7.62 46,7.9 IC1.54
  Top 0.813: CON1.4 v6.75,6.5
  Bottom 0.16: v43.81,6.99 43.81,6.03 42.86,5.08 7.62,5.08 6.75,5.95 v6.75,6.5 6.75,6.75 7.3,7.3 8.26,7.3 8.89,7.94 10.79,7.94 11.11,8.26 11.75,8.26 12.38,8.89 14.29,8.89 14.92,9.53 16.51,9.53 17.46,10.48 20.32,10.48 21.27,11.43 23.81,11.43 24.45,12.06 26.04,12.06 30.16,16.19 30.16,17.78 v30.48,18.1
NWR  (via drill 0.4)
  Top 0.16: IC1.55 46.5,9.67 46.67,9.84 47.62,9.84 47.94,9.53 v47.94,7.94 | IC6.1 20.97,28.88 23.81,26.04 25.4,26.04 31.43,20 v31.43,18.41
  Top 0.813: CON1.3 v5.25,6.5
  Bottom 0.16: v47.94,7.94 47.62,7.94 44.13,4.45 6.03,4.45 5.25,5.23 v5.25,6.5 5.25,6.84 5.71,7.3 6.67,7.3 6.99,7.62 7.94,7.62 8.57,8.26 10.48,8.26 10.79,8.57 11.43,8.57 12.06,9.21 13.97,9.21 14.61,9.84 16.19,9.84 17.14,10.79 20,10.79 20.95,11.75 23.5,11.75 24.13,12.38 25.72,12.38 29.84,16.51 29.84,18.41 30.16,18.73 31.11,18.73 v31.43,18.41

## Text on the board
Top: GBA | Flashcart | V1.0
Bottom: 02/05 | DL9SEC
